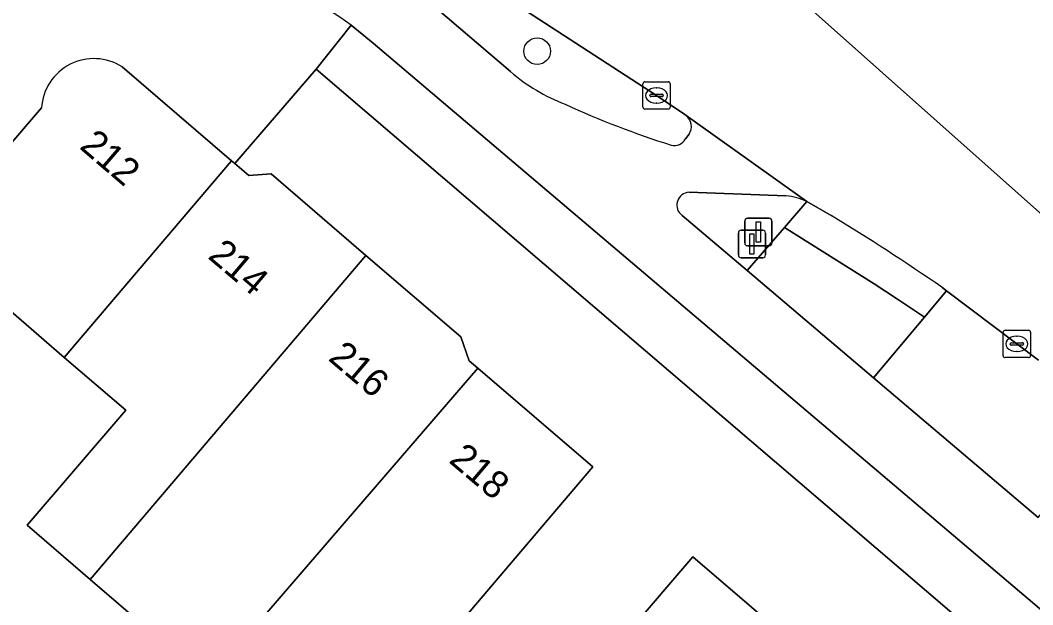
# Model space of a CAD drawing. Extents: x 162344 to 162869, y 381217 to 381818.
# Drawn here: x 162518.08 to 162555.05, y 381775.7 to 381797.06 of the extents above; entities that cross this region are included whole.
import ezdxf

# ---------------------------------------------------------------- set-up
doc = ezdxf.new("R2010")
doc.units = 0
for name, color, linetype in [('IMGEO_Berm_groen', 7, 'Continuous'), ('IMGEO_Berm_open', 7, 'Continuous'), ('IMGEO_Boom', 7, 'Continuous'), ('IMGEO_Erf', 7, 'Continuous'), ('IMGEO_Fietspad_gesloten', 7, 'Continuous'), ('IMGEO_Kolk', 7, 'Continuous'), ('IMGEO_Lichtmast', 7, 'Continuous'), ('IMGEO_Pand', 7, 'Continuous'), ('IMGEO_Pand_nummerreeks', 7, 'Continuous'), ('IMGEO_Rijbaan_lokaal_gesloten', 7, 'Continuous'), ('IMGEO_Verkeersbordpaal', 7, 'Continuous'), ('IMGEO_Verkeerseiland_groen', 7, 'Continuous'), ('IMGEO_Voetpad_open', 7, 'Continuous')]:
    doc.layers.add(name, color=color, linetype=linetype)

msp = doc.modelspace()

# ---------------------------------------------------------------- linework, layer by layer
at = {"layer": 'IMGEO_Berm_groen'}
msp.add_lwpolyline([(162555.268, 381784.639), (162554.472, 381785.229), (162551.904, 381787.167), (162551.096, 381786.201), (162549.242, 381783.987), (162555.254, 381778.882), (162556.553, 381780.481)], dxfattribs=at)
at = {"layer": 'IMGEO_Berm_open'}
msp.add_lwpolyline([(162551.096, 381786.201), (162550.108, 381786.864), (162549.257, 381787.43), (162545.983, 381789.478), (162544.625, 381787.907), (162549.242, 381783.987)], close=True, dxfattribs=at)
at = {"layer": 'IMGEO_Boom'}
msp.add_circle((162536.958, 381795.925), 0.489, dxfattribs=at)
at = {"layer": 'IMGEO_Erf'}
for points in [[(162581.778, 381750), (162528.884, 381795.273), (162525.921, 381791.816), (162526.43, 381791.378), (162527.242, 381791.44), (162530.708, 381788.463), (162534.173, 381785.486), (162534.48, 381784.612), (162534.792, 381784.344), (162538.993, 381780.735), (162534.29, 381775.205)], [(162524.95, 381772.924), (162520.639, 381776.627), (162518.332, 381778.608), (162521.939, 381782.807), (162519.691, 381784.738), (162517.175, 381786.899)], [(162537.922, 381771.935), (162542.644, 381777.449), (162546.834, 381773.85)]]:
    msp.add_lwpolyline(points, dxfattribs=at)
at = {"layer": 'IMGEO_Fietspad_gesloten'}
for points in [[(162535.98, 381795.182), (162532.926, 381797.791), (162532.162, 381798.458), (162532.122, 381798.501)], [(162530.162, 381796.875), (162530.974, 381796.217), (162578.489, 381755.878), (162611.83, 381727.598), (162620.898, 381719.907), (162656.302, 381689.888), (162668.485, 381679.538), (162672.31, 381676.305)], [(162546.807, 381790.431), (162542.392, 381793.581)], [(162542.504, 381792.89), (162542.371, 381792.719)], [(162542.51, 381790.77), (162546.042, 381790.644)], [(162555.254, 381778.882), (162549.242, 381783.987), (162544.625, 381787.907), (162542.255, 381789.919)]]:
    msp.add_lwpolyline(points, dxfattribs=at)
for centre, radius, start, end in [((162523.033, 381787.25), 11.978, 53.4724, 72.4775), ((162540.493, 381800.446), 6.934, 229.391, 248.7405), ((162552.493, 381825.872), 35.036, 245.5277, 252.316), ((162542.067, 381793.174), 0.521, 327.0291, 51.3842), ((162541.967, 381792.934), 0.457, 255.1251, 331.9605), ((162542.528, 381790.301), 0.47, 92.2296, 234.4089), ((162545.745, 381788.097), 2.564, 65.5334, 83.3489)]:
    msp.add_arc(centre, radius, start, end, dxfattribs=at)
at = {"layer": 'IMGEO_Kolk'}
for p, q in [((162540.891, 381794.807), (162541.743, 381794.807)), ((162540.816, 381793.881), (162540.816, 381794.733)), ((162541.304, 381794.587), (162541.329, 381794.587)), ((162541.817, 381794.733), (162541.817, 381793.881)), ((162541.075, 381794.301), (162541.075, 381794.313)), ((162541.513, 381794.264), (162541.115, 381794.264)), ((162541.118, 381794.35), (162541.516, 381794.35)), ((162541.559, 381794.313), (162541.559, 381794.301)), ((162541.743, 381793.807), (162540.891, 381793.807)), ((162541.327, 381794.027), (162541.302, 381794.027)), ((162553.971, 381784.803), (162553.971, 381785.655)), ((162554.046, 381785.729), (162554.898, 381785.729)), ((162554.972, 381785.655), (162554.972, 381784.803)), ((162554.23, 381785.223), (162554.23, 381785.235)), ((162554.668, 381785.186), (162554.27, 381785.186)), ((162554.273, 381785.272), (162554.671, 381785.272)), ((162554.459, 381785.509), (162554.484, 381785.509)), ((162554.714, 381785.235), (162554.714, 381785.223)), ((162554.482, 381784.949), (162554.457, 381784.949)), ((162554.898, 381784.729), (162554.046, 381784.729))]:
    msp.add_line(p, q, dxfattribs=at)
for points in [[(162540.891, 381794.807), (162541.743, 381794.807)], [(162540.816, 381793.881), (162540.816, 381794.733)], [(162541.817, 381794.733), (162541.817, 381793.881)], [(162541.743, 381793.807), (162540.891, 381793.807)], [(162553.971, 381784.803), (162553.971, 381785.655)], [(162554.046, 381785.729), (162554.898, 381785.729)], [(162554.972, 381785.655), (162554.972, 381784.803)], [(162554.898, 381784.729), (162554.046, 381784.729)]]:
    msp.add_lwpolyline(points, dxfattribs=at)
for centre, radius, start, end in [((162540.893, 381794.731), 0.0765, 91.552, 178.448), ((162540.893, 381794.731), 0.0765, 91.552, 178.448), ((162541.741, 381794.731), 0.0765, 1.552, 88.448), ((162541.741, 381794.731), 0.0765, 1.552, 88.448), ((162541.115, 381794.31), 0.0403, 85.8775, 175.7526), ((162541.112, 381794.3), 0.0366, 178.938, 274.7102), ((162541.516, 381794.307), 0.043, 264.8664, 352.4533), ((162541.52, 381794.312), 0.0386, 1.7309, 96.639), ((162540.893, 381793.883), 0.0765, 181.552, 268.448), ((162540.893, 381793.883), 0.0765, 181.552, 268.448), ((162541.741, 381793.883), 0.0765, 271.552, 358.448), ((162541.741, 381793.883), 0.0765, 271.552, 358.448), ((162554.048, 381785.653), 0.0765, 91.552, 178.448), ((162554.048, 381785.653), 0.0765, 91.552, 178.448), ((162554.896, 381785.653), 0.0765, 1.552, 88.448), ((162554.896, 381785.653), 0.0765, 1.552, 88.448), ((162554.27, 381785.232), 0.0403, 85.8775, 175.7526), ((162554.267, 381785.222), 0.0366, 178.938, 274.7102), ((162554.671, 381785.229), 0.043, 264.8664, 352.4533), ((162554.675, 381785.234), 0.0386, 1.7309, 96.639), ((162554.048, 381784.805), 0.0765, 181.552, 268.448), ((162554.048, 381784.805), 0.0765, 181.552, 268.448), ((162554.896, 381784.805), 0.0765, 271.552, 358.448), ((162554.896, 381784.805), 0.0765, 271.552, 358.448)]:
    msp.add_arc(centre, radius, start, end, dxfattribs=at)
for centre, major_axis, ratio, start_param, end_param in [((162541.303, 381794.307), (-0.387, 0.002), 0.722429, 4.712389, 7.853982), ((162541.328, 381794.307), (-0.39, 0.002), 0.717154, 1.570796, 4.712389), ((162554.458, 381785.229), (-0.387, 0.002), 0.722429, 4.712389, 7.853982), ((162554.483, 381785.229), (-0.39, 0.002), 0.717154, 1.570796, 4.712389)]:
    msp.add_ellipse(centre, major_axis=major_axis, ratio=ratio, start_param=start_param, end_param=end_param, dxfattribs=at)
at = {"layer": 'IMGEO_Lichtmast'}
for p, q in [((162544.304, 381788.48), (162544.304, 381789.28)), ((162544.304, 381789.28), (162544.304, 381788.48)), ((162544.404, 381789.38), (162545.194, 381789.38)), ((162545.194, 381789.38), (162544.404, 381789.38)), ((162545.294, 381789.28), (162545.294, 381788.48)), ((162545.294, 381788.48), (162545.294, 381789.28)), ((162545.194, 381788.38), (162544.404, 381788.38)), ((162544.404, 381788.38), (162545.194, 381788.38))]:
    msp.add_line(p, q, dxfattribs=at)
msp.add_lwpolyline([(162544.724, 381789.255), (162544.874, 381789.255), (162544.874, 381788.505), (162544.724, 381788.505), (162544.724, 381789.255)], dxfattribs=at)
for centre, start, end in [((162544.404, 381789.28), 90, 180), ((162544.404, 381789.28), 90, 180), ((162545.194, 381789.28), 0, 90), ((162545.194, 381789.28), 360, 90), ((162544.404, 381788.48), 180, 270), ((162544.404, 381788.48), 180, 270), ((162545.194, 381788.48), 270, 0), ((162545.194, 381788.48), 270, 0)]:
    msp.add_arc(centre, 0.1, start, end, dxfattribs=at)
at = {"layer": 'IMGEO_Pand'}
msp.add_lwpolyline([(162518.862, 381793.853), (162516.026, 381790.552), (162515.41, 381791.081), (162511.997, 381787.108), (162511.88, 381786.972), (162514.963, 381784.324), (162517.175, 381786.899), (162519.691, 381784.738), (162525.8, 381791.919), (162521.807, 381795.349)], dxfattribs=at)
for points in [[(162520.639, 381776.627), (162530.708, 381788.463), (162527.242, 381791.44), (162526.43, 381791.378), (162525.921, 381791.816), (162525.8, 381791.919), (162519.691, 381784.738), (162521.939, 381782.807), (162518.332, 381778.608)], [(162534.792, 381784.344), (162534.48, 381784.612), (162534.173, 381785.486), (162530.708, 381788.463), (162520.639, 381776.627), (162524.95, 381772.924)], [(162534.458, 381775.063), (162534.29, 381775.205), (162538.993, 381780.735), (162534.792, 381784.344), (162524.95, 381772.924), (162523.954, 381771.765), (162525.906, 381770.088), (162527.328, 381768.866), (162524.282, 381765.32), (162527.053, 381762.94), (162531.492, 381768.158), (162529.63, 381769.834), (162530.283, 381770.594), (162530.5, 381770.409)], [(162538.745, 381768.41), (162540.722, 381766.711), (162540.889, 381766.907), (162546.834, 381773.85), (162542.644, 381777.449), (162537.922, 381771.935), (162537.755, 381772.079), (162533.788, 381767.446), (162534.018, 381767.249), (162533.357, 381766.479), (162531.492, 381768.158), (162527.053, 381762.94), (162529.947, 381760.454), (162532.866, 381763.852), (162534.93, 381766.255), (162535.696, 381765.596), (162536.06, 381765.284)]]:
    msp.add_lwpolyline(points, close=True, dxfattribs=at)
msp.add_arc((162520.772, 381793.741), 1.913, 57.2245, 176.6348, dxfattribs=at)
at = {"layer": 'IMGEO_Rijbaan_lokaal_gesloten'}
for points in [[(162682.885, 381679.37), (162660.039, 381699.143), (162564.766, 381781.599), (162531.941, 381810.835), (162531.76, 381810.666), (162534.637, 381807.721), (162534.665, 381807.693), (162538.071, 381804.24), (162539.651, 381802.697)], [(162529.183, 381802.18), (162533.097, 381799.629), (162533.177, 381799.58), (162533.38, 381799.468), (162541.317, 381794.307), (162542.345, 381793.615), (162542.392, 381793.581), (162546.807, 381790.431), (162547.695, 381789.925)], [(162551.732, 381787.297), (162551.904, 381787.167), (162554.472, 381785.229), (162555.268, 381784.639)]]:
    msp.add_lwpolyline(points, dxfattribs=at)
msp.add_arc((162502.063, 381715.412), 87.376, 55.35718, 58.5163, dxfattribs=at)
at = {"layer": 'IMGEO_Verkeersbordpaal'}
for p, q in [((162544.538, 381788.918), (162544.538, 381789.718)), ((162544.538, 381789.718), (162544.538, 381788.918)), ((162544.638, 381789.818), (162545.428, 381789.818)), ((162545.428, 381789.818), (162544.638, 381789.818)), ((162545.528, 381789.718), (162545.528, 381788.918)), ((162545.528, 381788.918), (162545.528, 381789.718)), ((162545.428, 381788.818), (162544.638, 381788.818)), ((162544.638, 381788.818), (162545.428, 381788.818))]:
    msp.add_line(p, q, dxfattribs=at)
msp.add_lwpolyline([(162544.958, 381789.693), (162545.108, 381789.693), (162545.108, 381788.943), (162544.958, 381788.943), (162544.958, 381789.693)], dxfattribs=at)
for centre, start, end in [((162544.638, 381789.718), 90, 180), ((162544.638, 381789.718), 90, 180), ((162545.428, 381789.718), 0, 90), ((162545.428, 381789.718), 360, 90), ((162544.638, 381788.918), 180, 270), ((162544.638, 381788.918), 180, 270), ((162545.428, 381788.918), 270, 0), ((162545.428, 381788.918), 270, 0)]:
    msp.add_arc(centre, 0.1, start, end, dxfattribs=at)
at = {"layer": 'IMGEO_Verkeerseiland_groen'}
for points in [[(162542.392, 381793.581), (162542.345, 381793.615), (162541.317, 381794.307), (162533.38, 381799.468)], [(162532.122, 381798.501), (162532.162, 381798.458), (162532.926, 381797.791), (162535.98, 381795.182)], [(162542.371, 381792.719), (162542.504, 381792.89)], [(162546.042, 381790.644), (162542.51, 381790.77)], [(162542.255, 381789.919), (162544.625, 381787.907), (162545.983, 381789.478), (162546.807, 381790.431)]]:
    msp.add_lwpolyline(points, dxfattribs=at)
for centre, radius, start, end in [((162540.493, 381800.446), 6.934, 229.391, 248.7405), ((162552.493, 381825.872), 35.036, 245.5277, 252.316), ((162542.067, 381793.174), 0.521, 327.0291, 51.3842), ((162541.967, 381792.934), 0.457, 255.1251, 331.9605), ((162542.528, 381790.301), 0.47, 92.2296, 234.4089), ((162545.745, 381788.097), 2.564, 65.5334, 83.3489)]:
    msp.add_arc(centre, radius, start, end, dxfattribs=at)
at = {"layer": 'IMGEO_Voetpad_open'}
for points in [[(162521.807, 381795.349), (162525.8, 381791.919), (162525.921, 381791.816), (162528.884, 381795.273), (162530.162, 381796.875)], [(162578.489, 381755.878), (162530.974, 381796.217), (162530.162, 381796.875), (162528.884, 381795.273), (162581.778, 381750)], [(162477.365, 381760.866), (162480.048, 381763.094), (162482.459, 381765.097), (162484.202, 381766.545), (162485.213, 381767.386), (162487.804, 381769.538), (162495.941, 381775.556), (162497.567, 381773.375), (162500.549, 381775.618), (162498.939, 381777.8), (162503.234, 381781.172), (162506.332, 381783.699), (162511.324, 381787.606), (162511.997, 381787.108), (162515.41, 381791.081), (162516.026, 381790.552), (162518.862, 381793.853)], [(162547.695, 381789.925), (162546.807, 381790.431), (162545.983, 381789.478), (162549.257, 381787.43), (162550.108, 381786.864), (162551.096, 381786.201), (162551.904, 381787.167), (162551.732, 381787.297)]]:
    msp.add_lwpolyline(points, dxfattribs=at)
for centre, radius, start, end in [((162523.033, 381787.25), 11.978, 53.4724, 72.4775), ((162520.772, 381793.741), 1.913, 57.2245, 176.6348), ((162502.063, 381715.412), 87.376, 55.35718, 58.5163)]:
    msp.add_arc(centre, radius, start, end, dxfattribs=at)

# ---------------------------------------------------------------- texts
at = {"layer": 'IMGEO_Pand_nummerreeks'}
for s, rotation, p in [('212', 319.3385, (162520.211, 381792.396)), ('214', 319.7109, (162524.896, 381788.386)), ('216', 319.7096, (162529.293, 381784.658)), ('218', 319.7096, (162533.695, 381780.927))]:
    msp.add_text(s, height=1, rotation=rotation, dxfattribs=at).set_placement(p)

doc.saveas('drawing.dxf')
